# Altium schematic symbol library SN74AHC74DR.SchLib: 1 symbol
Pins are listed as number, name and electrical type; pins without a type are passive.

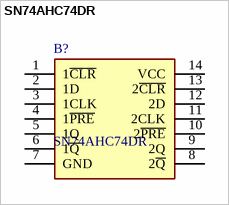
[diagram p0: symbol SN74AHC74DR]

## SN74AHC74DR
designator B?
Dual Positive-Edge-Triggered D-Type Flip-Flops With Clear and Preset; Manufacturer_Name: Texas Instruments; Geometry.Height: 1.75mm
footprint SOIC127P600X175-14N
pins: 1 1~{CLR}, 2 1D, 3 1CLK, 4 1~{PRE}, 5 1Q, 6 1~{Q}, 7 GND, 8 2~{Q}, 9 2Q, 10 2~{PRE}, 11 2CLK, 12 2D, 13 2~{CLR}, 14 VCC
